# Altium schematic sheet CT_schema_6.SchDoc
size 308 x 321 mm
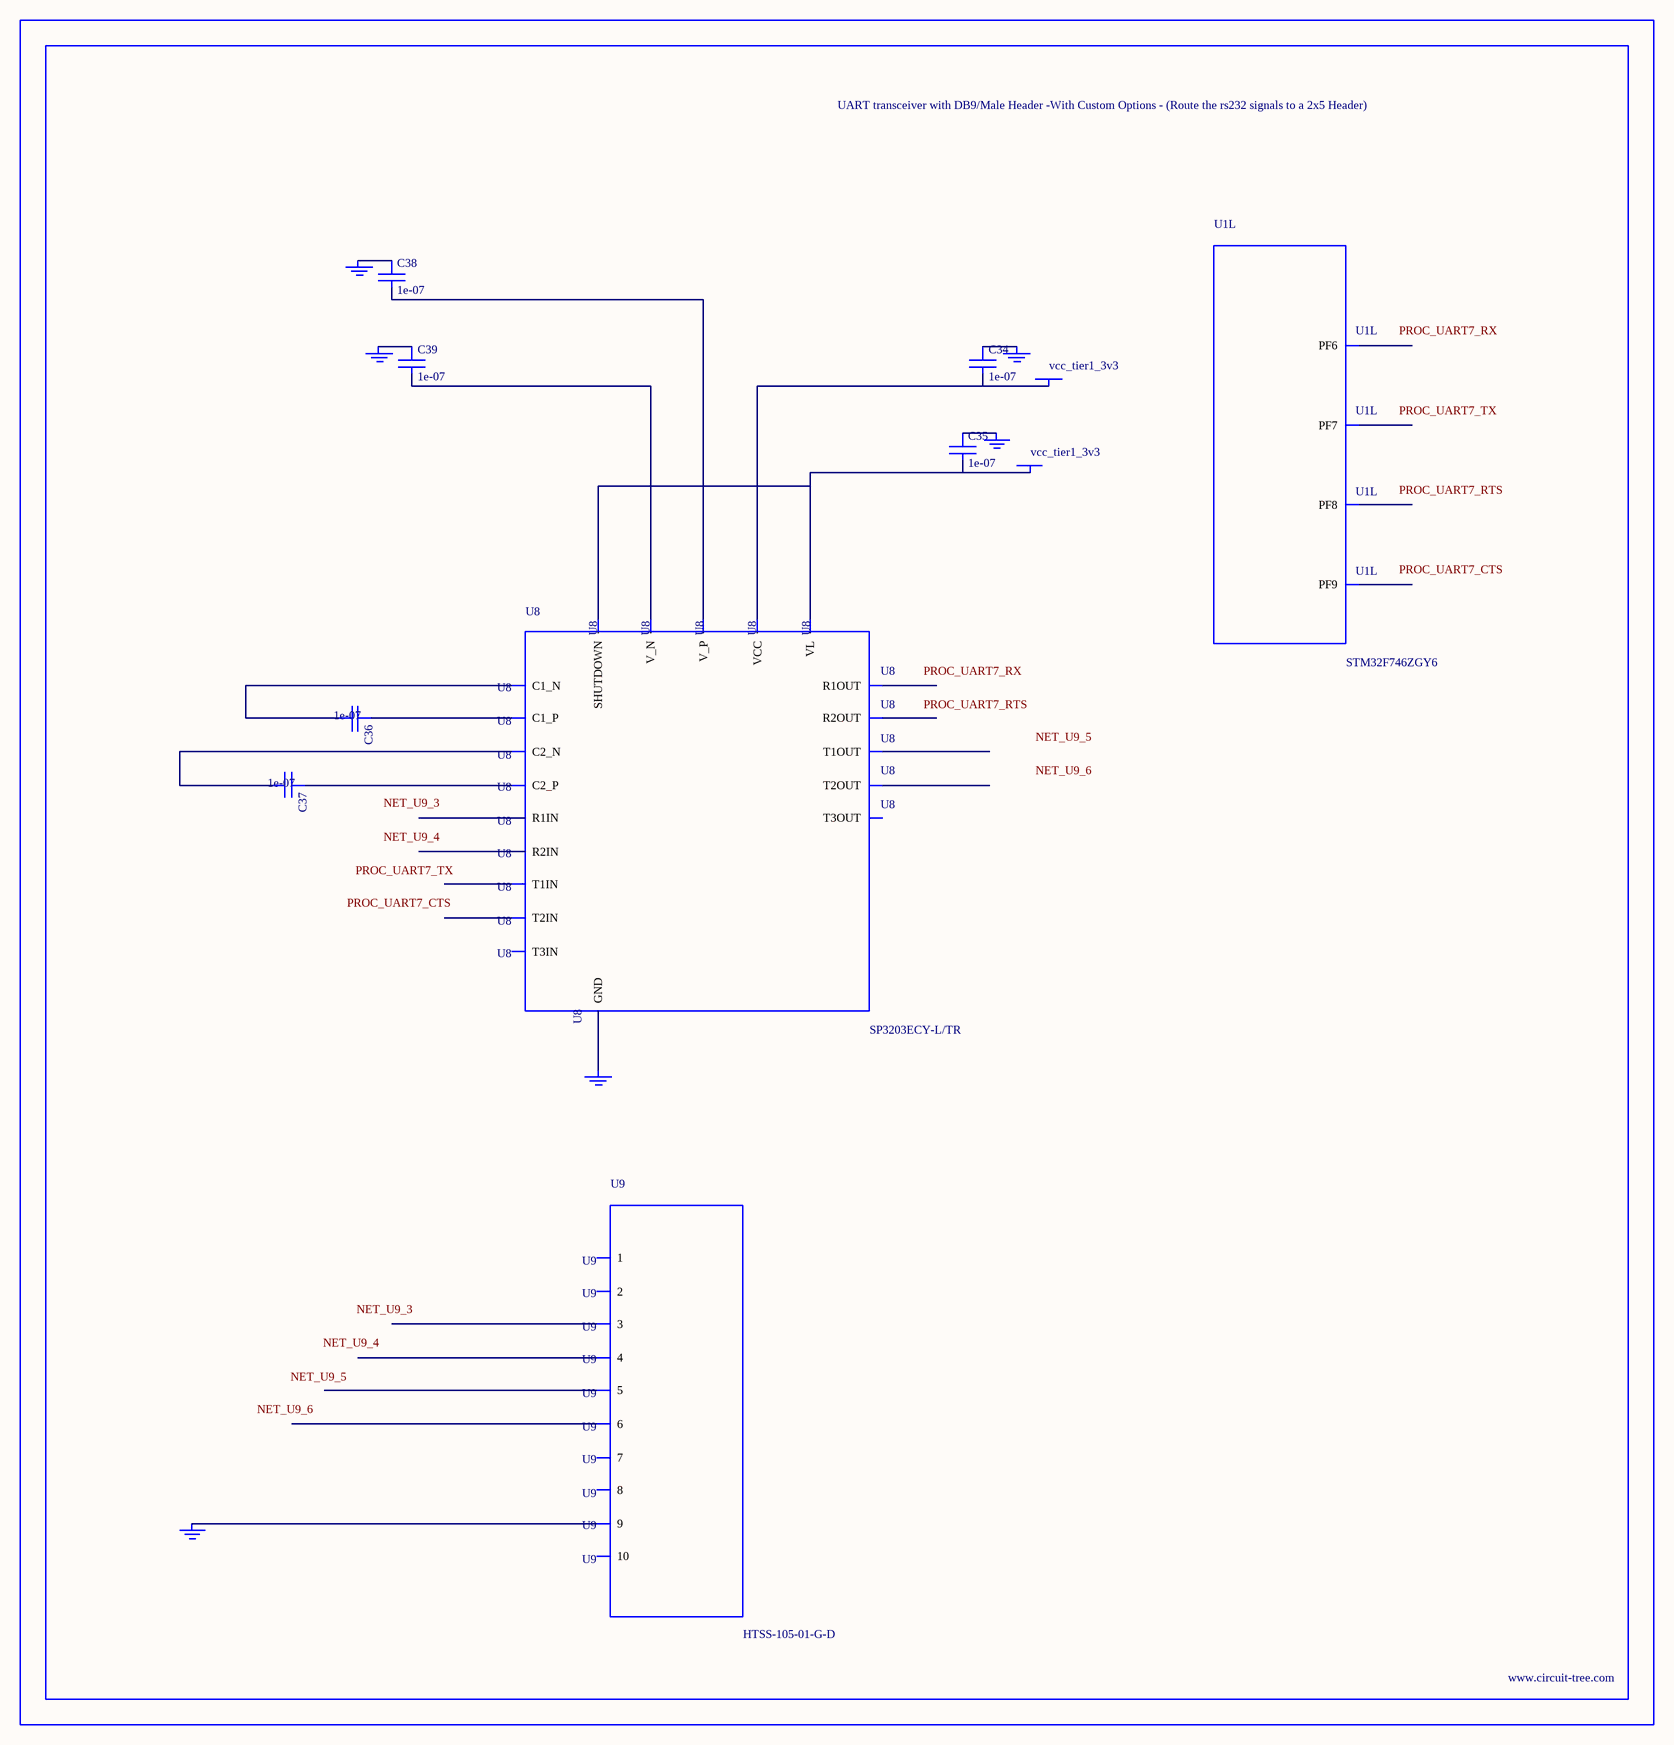
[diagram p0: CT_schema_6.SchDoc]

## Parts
BORDER5  (no value)
C34  1e-07  [C0402]
C35  1e-07  [C0402]
C36  1e-07  [C0402]
C37  1e-07  [C0402]
C38  1e-07  [C0402]
C39  1e-07  [C0402]
GND_INSTANCE_5_0  (no value)
GND_INSTANCE_5_1  (no value)
GND_INSTANCE_5_2  (no value)
GND_INSTANCE_5_3  (no value)
GND_INSTANCE_5_4  (no value)
GND_INSTANCE_5_5  (no value)
POWER_INSTANCE_5_0  vcc_tier1_3v3
POWER_INSTANCE_5_1  vcc_tier1_3v3
U1  STM32F746ZGY6  [WLCSP143]  (part L of 13)
U8  SP3203ECY-L/TR  [TSSOP20-I]
U9  HTSS-105-01-G-D  [HTSS-105-01-G-D]

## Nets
NetC34_1: C34.1 GND_INSTANCE_5_3.0(GND)
NetC34_2: C34.2 POWER_INSTANCE_5_1.0(PWR) U8.19(VCC)
NetC35_1: C35.1 GND_INSTANCE_5_2.0(GND)
NetC35_2: C35.2 POWER_INSTANCE_5_0.0(PWR) U8.12(VL) U8.20(SHUTDOWN)
NetC36_1: C36.1 U8.1(C1_P)
NetC36_2: C36.2 U8.3(C1_N)
NetC37_1: C37.1 U8.4(C2_P)
NetC37_2: C37.2 U8.5(C2_N)
NetC38_1: C38.1 GND_INSTANCE_5_0.0(GND)
NetC38_2: C38.2 U8.2(V_P)
NetC39_1: C39.1 GND_INSTANCE_5_1.0(GND)
NetC39_2: C39.2 U8.6(V_N)
NetGND_INSTANCE_5_4_0: GND_INSTANCE_5_4.0(GND) U8.18(GND)
NetGND_INSTANCE_5_5_0: GND_INSTANCE_5_5.0(GND) U9.9

Not connected (* = marked no-connect by the designer): U1 F7(PF7) G8(PF9) G10(PF6) H11(PF8); U8 7(T1IN) 8(T2IN) 9(T3IN) 10(R2OUT) 11(R1OUT) 13(R2IN) 14(R1IN) 15(T3OUT) 16(T2OUT) 17(T1OUT); U9 1 2 3 4 5 6 7 8 10

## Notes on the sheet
- Labels drawn without touching a wire or pin: NET_U9_3, NET_U9_4, NET_U9_5, NET_U9_6, PROC_UART7_CTS, PROC_UART7_RTS, PROC_UART7_RX, PROC_UART7_TX

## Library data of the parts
BORDER5 = BORDER_PAGE5
C34-C39 = C0402C104K3RACTU
GND_INSTANCE_5_0-GND_INSTANCE_5_5 = GND
POWER_INSTANCE_5_0 POWER_INSTANCE_5_1 = PWR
